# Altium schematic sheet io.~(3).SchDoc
size Letter
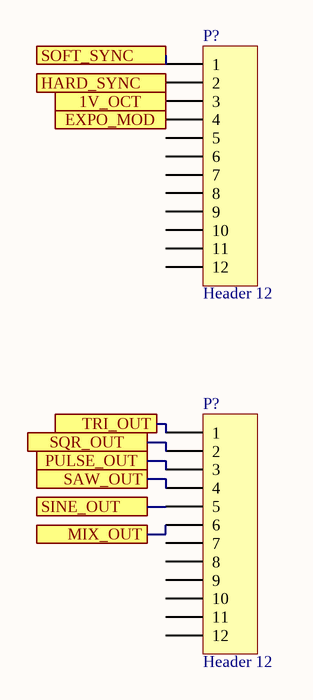
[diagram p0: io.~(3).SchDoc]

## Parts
(Parts that share a designator on the sheet are numbered #1, #2 ... from top to bottom, then left to right.)
P?#1  Header 12  [HDR1X12]
P?#2  Header 12  [HDR1X12]

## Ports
1V_OCT, EXPO_MOD, HARD_SYNC, MIX_OUT, PULSE_OUT, SAW_OUT, SINE_OUT, SOFT_SYNC, SQR_OUT, TRI_OUT

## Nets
1V_OCT: P?#1.3 ; port 1V_OCT
EXPO_MOD: P?#1.4 ; port EXPO_MOD
HARD_SYNC: P?#1.2 ; port HARD_SYNC
MIX_OUT: P?#2.6 ; port MIX_OUT
PULSE_OUT: P?#2.3 ; port PULSE_OUT
SAW_OUT: P?#2.4 ; port SAW_OUT
SINE_OUT: P?#2.5 ; port SINE_OUT
SOFT_SYNC: P?#1.1 ; port SOFT_SYNC
SQR_OUT: P?#2.2 ; port SQR_OUT
TRI_OUT: P?#2.1 ; port TRI_OUT

Not connected (* = marked no-connect by the designer): P?#1 5 6 7 8 9 10 11 12; P?#2 7 8 9 10 11 12

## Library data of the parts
P?#1 P?#2 = Header 12: Header, 12-Pin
